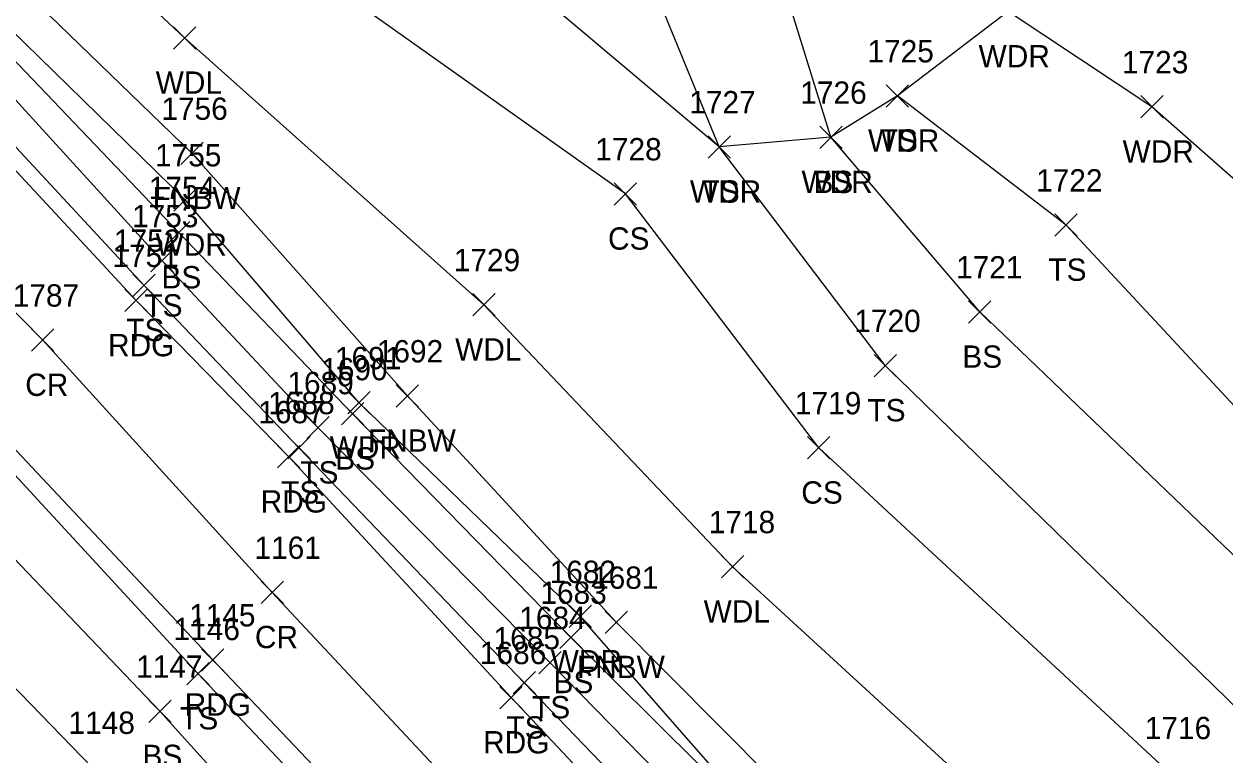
# Model space of a CAD drawing. Extents: x 1469310 to 1475157, y 493997 to 498873.
# Drawn here: x 1469401.2 to 1469508.8, y 498727 to 498792.5 of the extents above; entities that cross this region are included whole.
import ezdxf

# ---------------------------------------------------------------- set-up
doc = ezdxf.new("R2010")
doc.units = 0
for name, color, linetype in [('L_A', 7, 'Continuous'), ('L_I', 7, 'Continuous'), ('L_TIC', 7, 'Continuous'), ('LAWA', 7, 'Continuous'), ('LELB', 7, 'Continuous'), ('LFNC', 7, 'Continuous'), ('P_A', 7, 'Continuous'), ('P_I', 7, 'Continuous'), ('P_TIC', 7, 'Continuous'), ('PEU', 7, 'Continuous'), ('PRC', 7, 'Continuous')]:
    doc.layers.add(name, color=color, linetype=linetype)

msp = doc.modelspace()

# ---------------------------------------------------------------- linework, layer by layer
at = {"layer": 'L_TIC'}
for points in [[(1469414.63, 498790.26), (1469416.63, 498792.26)], [(1469416.63, 498790.26), (1469414.63, 498792.26)], [(1469478.51, 498785.07), (1469480.51, 498787.07)], [(1469480.51, 498785.07), (1469478.51, 498787.07)], [(1469478.51, 498785.07), (1469480.51, 498787.07)], [(1469480.51, 498785.07), (1469478.51, 498787.07)], [(1469501.31, 498784.09), (1469503.31, 498786.09)], [(1469503.31, 498784.09), (1469501.31, 498786.09)], [(1469462.54, 498780.5), (1469464.54, 498782.5)], [(1469464.54, 498780.5), (1469462.54, 498782.5)], [(1469462.54, 498780.5), (1469464.54, 498782.5)], [(1469464.54, 498780.5), (1469462.54, 498782.5)], [(1469472.54, 498781.36), (1469474.54, 498783.36)], [(1469474.54, 498781.36), (1469472.54, 498783.36)], [(1469472.54, 498781.36), (1469474.54, 498783.36)], [(1469474.54, 498781.36), (1469472.54, 498783.36)], [(1469415.3, 498779.92), (1469417.3, 498781.92)], [(1469417.3, 498779.92), (1469415.3, 498781.92)], [(1469454.13, 498776.29), (1469456.13, 498778.29)], [(1469456.13, 498776.29), (1469454.13, 498778.29)], [(1469414.67, 498775.75), (1469416.67, 498777.75)], [(1469416.67, 498775.75), (1469414.67, 498777.75)], [(1469493.62, 498773.5), (1469495.62, 498775.5)], [(1469495.62, 498773.5), (1469493.62, 498775.5)], [(1469414.11, 498772.82), (1469416.11, 498774.82)], [(1469416.11, 498772.82), (1469414.11, 498774.82)], [(1469412.62, 498770.3), (1469414.62, 498772.3)], [(1469414.62, 498770.3), (1469412.62, 498772.3)], [(1469410.99, 498768.1), (1469412.99, 498770.1)], [(1469412.99, 498768.1), (1469410.99, 498770.1)], [(1469441.45, 498766.36), (1469443.45, 498768.36)], [(1469443.45, 498766.36), (1469441.45, 498768.36)], [(1469485.88, 498765.71), (1469487.88, 498767.71)], [(1469487.88, 498765.71), (1469485.88, 498767.71)], [(1469477.41, 498760.91), (1469479.41, 498762.91)], [(1469479.41, 498760.91), (1469477.41, 498762.91)], [(1469434.59, 498758.19), (1469436.59, 498760.19)], [(1469436.59, 498758.19), (1469434.59, 498760.19)], [(1469430.27, 498757.58), (1469432.27, 498759.58)], [(1469432.27, 498757.58), (1469430.27, 498759.58)], [(1469429.69, 498756.59), (1469431.69, 498758.59)], [(1469431.69, 498756.59), (1469429.69, 498758.59)], [(1469426.59, 498755.34), (1469428.59, 498757.34)], [(1469428.59, 498755.34), (1469426.59, 498757.34)], [(1469424.87, 498753.55), (1469426.87, 498755.55)], [(1469426.87, 498753.55), (1469424.87, 498755.55)], [(1469471.45, 498753.54), (1469473.45, 498755.54)], [(1469473.45, 498753.54), (1469471.45, 498755.54)], [(1469463.73, 498742.89), (1469465.73, 498744.89)], [(1469465.73, 498742.89), (1469463.73, 498744.89)], [(1469450.08, 498738.43), (1469452.08, 498740.43)], [(1469452.08, 498738.43), (1469450.08, 498740.43)], [(1469453.31, 498737.91), (1469455.31, 498739.91)], [(1469455.31, 498737.91), (1469453.31, 498739.91)], [(1469449.25, 498736.56), (1469451.25, 498738.56)], [(1469451.25, 498736.56), (1469449.25, 498738.56)], [(1469447.36, 498734.3), (1469449.36, 498736.3)], [(1469449.36, 498734.3), (1469447.36, 498736.3)], [(1469415.82, 498733.31), (1469417.82, 498735.31)], [(1469417.82, 498733.31), (1469415.82, 498735.31)], [(1469445.06, 498732.49), (1469447.06, 498734.49)], [(1469447.06, 498732.49), (1469445.06, 498734.49)], [(1469412.42, 498729.94), (1469414.42, 498731.94)], [(1469414.42, 498729.94), (1469412.42, 498731.94)]]:
    msp.add_lwpolyline(points, dxfattribs=at)
at = {"layer": 'LAWA'}
for points in [[(1469639.57, 498698.43), (1469608.35, 498698.81), (1469602.51, 498699.12), (1469553.35, 498720.92), (1469557.66, 498736.35), (1469502.31, 498785.09), (1469489.42, 498793.62), (1469479.51, 498786.07), (1469473.54, 498782.36), (1469463.54, 498781.5), (1469427.61, 498811.79), (1469409.37, 498828.74), (1469393.62, 498848.43), (1469395.42, 498864.75)], [(1469550.26, 498635.87), (1469551.34, 498638.82), (1469543.79, 498653.66), (1469517, 498693.69), (1469493.7, 498717.29), (1469464.73, 498743.89), (1469442.45, 498767.36), (1469415.63, 498791.26), (1469396.51, 498809.17), (1469374.23, 498838.07)], [(1469550.26, 498635.87), (1469544.55, 498639.35), (1469529.26, 498656.59), (1469521.27, 498666.89), (1469499.1, 498691), (1469482.91, 498705.54), (1469469.32, 498718.6), (1469451.08, 498739.43), (1469431.27, 498758.58), (1469415.67, 498776.75), (1469392.18, 498799.73), (1469384.54, 498811.21)]]:
    msp.add_lwpolyline(points, dxfattribs=at)
at = {"layer": 'LELB'}
for points in [[(1469609.73, 498671.93), (1469579.3, 498664.24), (1469559.68, 498683.15), (1469537.62, 498706.16), (1469513.73, 498727.48), (1469478.41, 498761.91), (1469463.54, 498781.5), (1469454.7, 498803.05), (1469446.9, 498829.88), (1469451.16, 498846.1)], [(1469689.87, 498657.87), (1469664.2, 498669.39), (1469609.73, 498671.93), (1469582.14, 498658.76), (1469563.4, 498646.02), (1469554.48, 498659.45), (1469546.06, 498676.67), (1469525.38, 498698.23), (1469503.85, 498725.44), (1469472.45, 498754.54), (1469455.13, 498777.29), (1469419.87, 498802.33), (1469400.99, 498819.04), (1469383.05, 498844.76)], [(1469608.35, 498698.81), (1469602.82, 498680.15), (1469584.31, 498668.47), (1469565.41, 498686.22), (1469541.77, 498713.19), (1469523.97, 498731.2), (1469486.88, 498766.71), (1469473.54, 498782.36), (1469464.69, 498810.88), (1469465.59, 498843.26)], [(1469469.32, 498718.6), (1469450.25, 498737.56), (1469430.69, 498757.59), (1469415.11, 498773.82), (1469391.34, 498798.74), (1469366.13, 498825.62)], [(1469596.34, 498559.71), (1469578.35, 498585.4), (1469563.74, 498607.63), (1469555.37, 498620.37), (1469550.82, 498626.65), (1469541.68, 498637.32), (1469517.52, 498662), (1469494.24, 498687.27), (1469477.2, 498705.84), (1469448.36, 498735.3), (1469427.59, 498756.34), (1469413.62, 498771.3), (1469390.02, 498797.18), (1469364.14, 498823.89)], [(1469563.74, 498607.63), (1469555.09, 498616.5), (1469548.65, 498625.25), (1469539.23, 498636.49), (1469516.21, 498660.23), (1469492, 498685.05), (1469474.24, 498704.18), (1469446.06, 498733.49), (1469425.87, 498754.55), (1469411.99, 498769.1), (1469387.95, 498794.99), (1469362.09, 498822.05)], [(1469602.51, 498699.12), (1469592.94, 498686.61), (1469572.77, 498690.91), (1469548.73, 498713.65), (1469531.24, 498735.14), (1469494.62, 498774.5), (1469479.51, 498786.07)], [(1469416.82, 498734.31), (1469396.87, 498755.94)], [(1469413.42, 498730.94), (1469392.79, 498752.52)], [(1469407.36, 498725.91), (1469385.28, 498748.65)], [(1469416.82, 498734.31), (1469446.33, 498703.1), (1469470.89, 498677.65), (1469509.28, 498636.71), (1469524.42, 498615.8), (1469544.37, 498592.02), (1469564.88, 498563.16), (1469574.6, 498542.86), (1469576.57, 498532.67), (1469562.98, 498525.95), (1469548.2, 498517.37), (1469540.61, 498511.22), (1469554.07, 498484.99), (1469566.51, 498459.59)], [(1469413.42, 498730.94), (1469442.52, 498698.7), (1469468.45, 498674.77), (1469500.53, 498635.82), (1469519, 498614.53), (1469533.17, 498594.86), (1469544.52, 498587.12), (1469562.89, 498554.7), (1469567.79, 498543.52), (1469559.26, 498528.6), (1469545.4, 498521.66), (1469536.79, 498513.03)]]:
    msp.add_lwpolyline(points, dxfattribs=at)
at = {"layer": 'LFNC'}
msp.add_lwpolyline([(1469557.57, 498626.92), (1469550.26, 498635.87), (1469522.29, 498667.62), (1469500.25, 498692.91), (1469472.78, 498720.33), (1469454.31, 498738.91), (1469435.59, 498759.19), (1469416.3, 498780.92), (1469395.2, 498801.33), (1469384.54, 498811.21), (1469367.12, 498829.45)], dxfattribs=at)
at = {"layer": 'P_TIC'}
for points in [[(1469410.28, 498766.74), (1469412.28, 498768.74)], [(1469412.28, 498766.74), (1469410.28, 498768.74)], [(1469401.92, 498763.19), (1469403.92, 498765.19)], [(1469403.92, 498763.19), (1469401.92, 498765.19)], [(1469423.97, 498752.74), (1469425.97, 498754.74)], [(1469425.97, 498752.74), (1469423.97, 498754.74)], [(1469422.49, 498740.59), (1469424.49, 498742.59)], [(1469424.49, 498740.59), (1469422.49, 498742.59)], [(1469417.16, 498734.54), (1469419.16, 498736.54)], [(1469419.16, 498734.54), (1469417.16, 498736.54)], [(1469443.89, 498731.16), (1469445.89, 498733.16)], [(1469445.89, 498731.16), (1469443.89, 498733.16)]]:
    msp.add_lwpolyline(points, dxfattribs=at)
at = {"layer": 'PEU'}
for points in [[(1469787.29, 498391.19), (1469770.79, 498403.19), (1469744.94, 498420.51), (1469711.23, 498443.77), (1469680.07, 498463.21), (1469651.58, 498483.41), (1469630.63, 498501.52), (1469612.52, 498523.24), (1469599.41, 498542.19), (1469591.57, 498556.6), (1469575.61, 498583.06), (1469557.31, 498607.49), (1469540.09, 498628.65), (1469536.24, 498634.99), (1469514.98, 498658.51), (1469490.83, 498684.27), (1469472.69, 498702.57), (1469444.89, 498732.16), (1469424.97, 498753.74), (1469411.28, 498767.74), (1469386.83, 498794.07), (1469360.47, 498820.44)], [(1469418.16, 498735.54), (1469397.76, 498757.22)], [(1469418.16, 498735.54), (1469447.91, 498704.22), (1469471.83, 498679.03), (1469509.9, 498637.99), (1469529.4, 498614.8), (1469545.14, 498594.13), (1469565.65, 498563.08), (1469576.41, 498543.24), (1469581.13, 498534.68), (1469591.75, 498510.08), (1469602.71, 498485.38), (1469609.03, 498458.44), (1469615.47, 498438.56), (1469621.98, 498404.81), (1469621.72, 498400.42), (1469625.38, 498362.57), (1469626.2, 498333.72)]]:
    msp.add_lwpolyline(points, dxfattribs=at)
at = {"layer": 'PRC'}
for points in [[(1469354.16, 498814.68), (1469376.82, 498790.67), (1469402.92, 498764.19)], [(1469423.49, 498741.59), (1469402.92, 498764.19)], [(1469423.49, 498741.59), (1469452.57, 498710.45), (1469477.96, 498685.46), (1469512.01, 498647.6), (1469532.7, 498623.32), (1469554.78, 498596.5), (1469570.66, 498571.79), (1469585.25, 498547.18), (1469603.31, 498509.95), (1469610.7, 498488.94), (1469623.7, 498439.14), (1469630.72, 498407.83), (1469631.04, 498401.91), (1469634.46, 498363.9), (1469634.52, 498333.31)]]:
    msp.add_lwpolyline(points, dxfattribs=at)

# ---------------------------------------------------------------- texts
at = {"layer": 'L_A'}
for s, p in [('WDR', (1469486.78, 498788.62)), ('WDL', (1469413.04, 498786.26)), ('WDR', (1469476.87, 498781.07)), ('TS', (1469477.92, 498781.07)), ('WDR', (1469499.68, 498780.09)), ('WDR', (1469470.91, 498777.36)), ('BS', (1469471.98, 498777.36)), ('WDR', (1469460.91, 498776.5)), ('TS', (1469461.95, 498776.5)), ('FNBW', (1469412.77, 498775.92)), ('CS', (1469453.57, 498772.29)), ('WDR', (1469413.03, 498771.75)), ('BS', (1469413.56, 498768.82)), ('TS', (1469493.03, 498769.5)), ('TS', (1469412.03, 498766.3)), ('TS', (1469410.4, 498764.1)), ('WDL', (1469439.87, 498762.36)), ('BS', (1469485.32, 498761.71)), ('TS', (1469476.82, 498756.91)), ('FNBW', (1469432.06, 498754.19)), ('WDR', (1469428.63, 498753.58)), ('BS', (1469429.13, 498752.59)), ('TS', (1469426, 498751.34)), ('TS', (1469424.28, 498749.55)), ('CS', (1469470.89, 498749.54)), ('WDL', (1469462.14, 498738.89)), ('WDR', (1469448.44, 498734.43)), ('FNBW', (1469450.79, 498733.91)), ('BS', (1469448.69, 498732.56)), ('TS', (1469446.77, 498730.3)), ('TS', (1469415.23, 498729.31)), ('TS', (1469444.47, 498728.49)), ('BS', (1469411.86, 498725.94))]:
    msp.add_text(s, height=2, dxfattribs=at).set_placement(p)
at = {"layer": 'L_I'}
for s, p in [('1725', (1469476.82, 498789.07)), ('1725', (1469476.82, 498789.07)), ('1723', (1469499.62, 498788.09)), ('1726', (1469470.8, 498785.36)), ('1726', (1469470.8, 498785.36)), ('1756', (1469413.55, 498783.92)), ('1727', (1469460.85, 498784.5)), ('1727', (1469460.85, 498784.5)), ('1755', (1469412.98, 498779.75)), ('1728', (1469452.43, 498780.29)), ('1722', (1469491.93, 498777.5)), ('1754', (1469412.42, 498776.82)), ('1753', (1469410.92, 498774.3)), ('1752', (1469409.3, 498772.1)), ('1729', (1469439.75, 498770.36)), ('1721', (1469484.76, 498769.71)), ('1720', (1469475.64, 498764.91)), ('1692', (1469432.85, 498762.19)), ('1691', (1469429.1, 498761.58)), ('1690', (1469427.87, 498760.59)), ('1689', (1469424.84, 498759.34)), ('1688', (1469423.13, 498757.55)), ('1719', (1469470.32, 498757.54)), ('1718', (1469462.6, 498746.89)), ('1682', (1469448.34, 498742.43)), ('1681', (1469452.14, 498741.91)), ('1683', (1469447.51, 498740.56)), ('1684', (1469445.62, 498738.3)), ('1146', (1469414.64, 498737.31)), ('1685', (1469443.32, 498736.49)), ('1147', (1469411.29, 498733.94)), ('1148', (1469405.23, 498728.91)), ('1716', (1469501.67, 498728.44))]:
    msp.add_text(s, height=2, dxfattribs=at).set_placement(p)
at = {"layer": 'P_A'}
for s, p in [('RDG', (1469408.77, 498762.74)), ('CR', (1469401.35, 498759.19)), ('RDG', (1469422.45, 498748.74)), ('CR', (1469421.93, 498736.59)), ('RDG', (1469415.64, 498730.54)), ('RDG', (1469442.38, 498727.16))]:
    msp.add_text(s, height=2, dxfattribs=at).set_placement(p)
at = {"layer": 'P_I'}
for s, p in [('1751', (1469409.16, 498770.74)), ('1787', (1469400.23, 498767.19)), ('1687', (1469422.23, 498756.74)), ('1161', (1469421.89, 498744.59)), ('1145', (1469416.03, 498738.54)), ('1686', (1469442.09, 498735.16))]:
    msp.add_text(s, height=2, dxfattribs=at).set_placement(p)

doc.saveas('drawing.dxf')
